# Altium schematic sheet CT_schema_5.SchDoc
size 300 x 247 mm
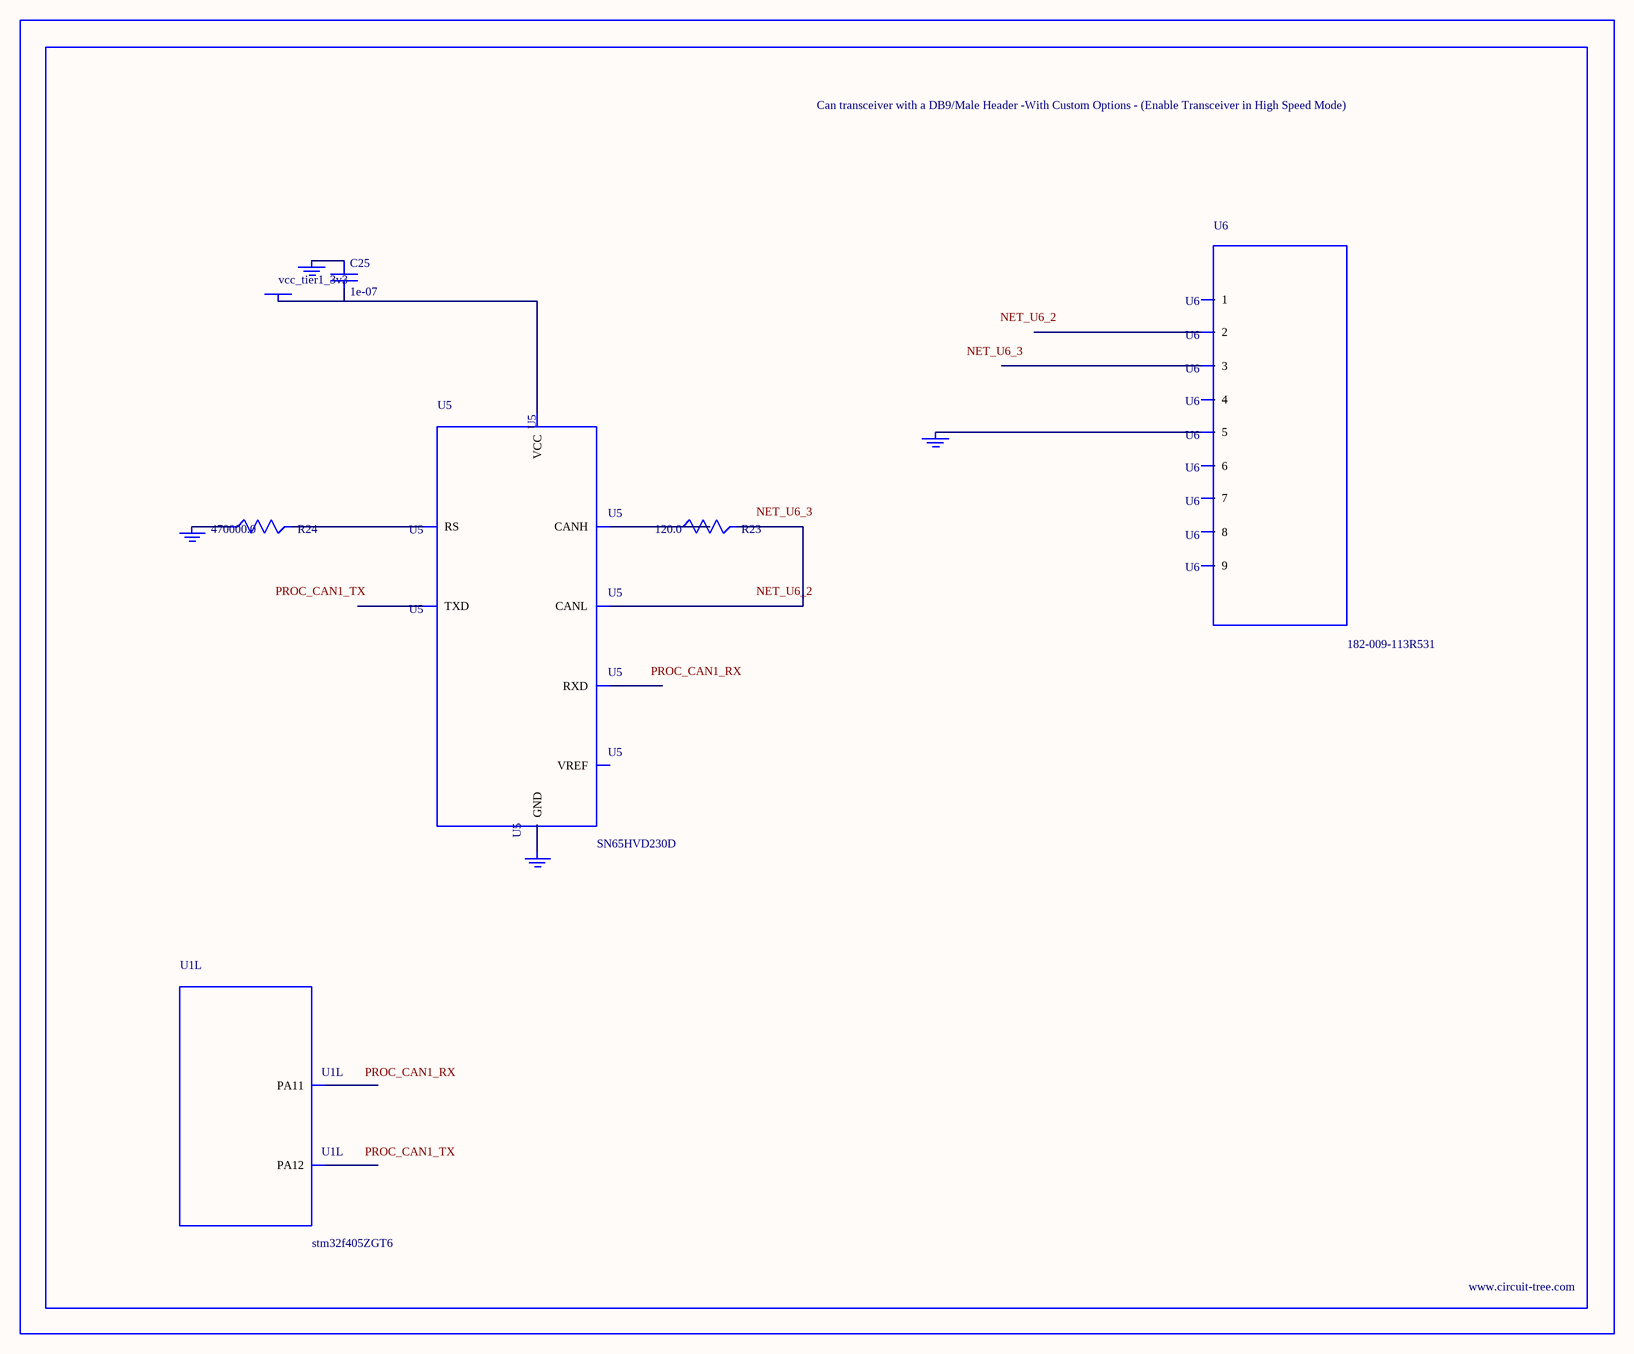
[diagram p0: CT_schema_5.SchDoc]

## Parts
BORDER4  (no value)
C25  1e-07  [C0402]
GND_INSTANCE_4_0  (no value)
GND_INSTANCE_4_1  (no value)
GND_INSTANCE_4_2  (no value)
GND_INSTANCE_4_3  (no value)
POWER_INSTANCE_4_0  vcc_tier1_3v3
R23  120.0  [R0603]
R24  470000.0  [R0603]
U1  stm32f405ZGT6  [LQFP144]  (part L of 13)
U5  SN65HVD230D  [SOIC-8]
U6  182-009-113R531  [182-009-MALE]

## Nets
NetC25_1: C25.1 GND_INSTANCE_4_0.0(GND)
NetC25_2: C25.2 POWER_INSTANCE_4_0.0(PWR) U5.3(VCC)
NetGND_INSTANCE_4_1_0: GND_INSTANCE_4_1.0(GND) R24.1
NetGND_INSTANCE_4_2_0: GND_INSTANCE_4_2.0(GND) U5.2(GND)
NetGND_INSTANCE_4_3_0: GND_INSTANCE_4_3.0(GND) U6.5
NetR23_1: R23.1 U5.7(CANH)
NetR23_2: R23.2 U5.6(CANL)
NetR24_2: R24.2 U5.8(RS)

Not connected (* = marked no-connect by the designer): U1 103(PA11) 104(PA12); U5 1(TXD) 4(RXD) 5(VREF); U6 1 2 3 4 6 7 8 9

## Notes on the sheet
- Labels drawn without touching a wire or pin: NET_U6_2, NET_U6_3, PROC_CAN1_RX, PROC_CAN1_TX

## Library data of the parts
BORDER4 = BORDER_PAGE4
C25 = C0402C104K3RACTU
GND_INSTANCE_4_0-GND_INSTANCE_4_3 = GND
POWER_INSTANCE_4_0 = PWR
R23 = RC0603JR-07120RL
R24 = RC0603JR-07470KL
